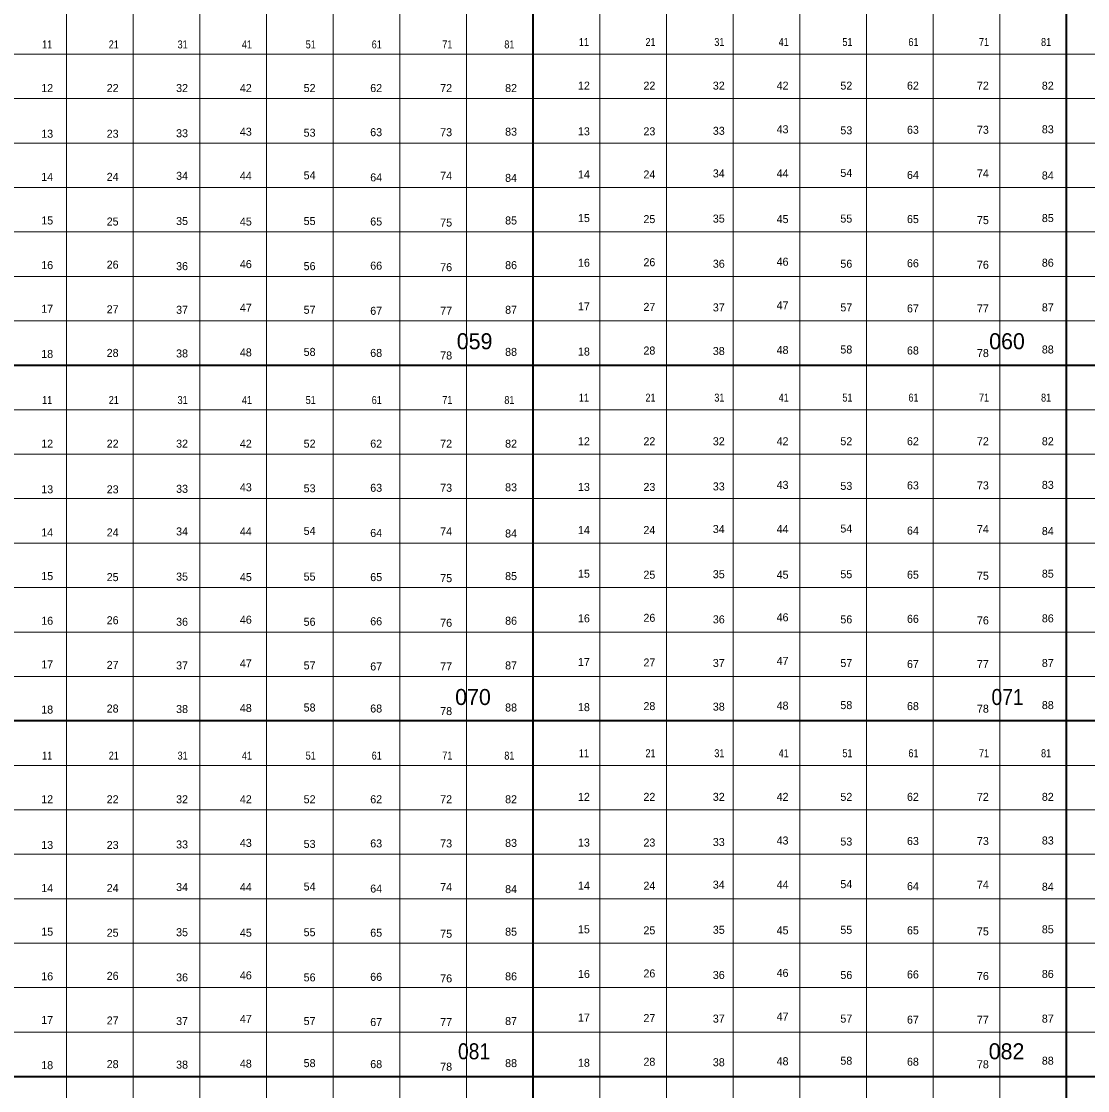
# Model space of a CAD drawing. Extents: x 639000 to 672000, y 222000 to 252000.
# Drawn here: x 660121 to 666119, y 233921 to 239934 of the extents above; entities that cross this region are included whole.
import ezdxf
from ezdxf.enums import TextEntityAlignment as Align

# ---------------------------------------------------------------- set-up
doc = ezdxf.new("R2010")
doc.units = 0
doc.header["$LTSCALE"] = 18
doc.layers.add('1', color=7, linetype='Continuous', lineweight=13)
doc.layers.add('2', color=7, linetype='Continuous')
doc.layers.add('29', color=7, linetype='Continuous')

msp = doc.modelspace()

# ---------------------------------------------------------------- linework, layer by layer
at = {"layer": '1'}
for p, q in [((660375, 224000), (660375, 246000)), ((660750, 224000), (660750, 246000)), ((661125, 224000), (661125, 246000)), ((661500, 224000), (661500, 246000)), ((661875, 224000), (661875, 246000)), ((662250, 224000), (662250, 246000)), ((662625, 224000), (662625, 246000)), ((663375, 230000), (663375, 244000)), ((663750, 230000), (663750, 244000)), ((664125, 230000), (664125, 244000)), ((664500, 230000), (664500, 244000)), ((664875, 230000), (664875, 244000)), ((665250, 230000), (665250, 244000)), ((665625, 230000), (665625, 244000)), ((639000, 239750), (672000, 239750)), ((639000, 239500), (672000, 239500)), ((639000, 239250), (672000, 239250)), ((639000, 239000), (672000, 239000)), ((639000, 238750), (672000, 238750)), ((639000, 238500), (672000, 238500)), ((639000, 238250), (672000, 238250)), ((672000, 237750), (639000, 237750)), ((672000, 237500), (639000, 237500)), ((672000, 237250), (639000, 237250)), ((672000, 237000), (639000, 237000)), ((672000, 236750), (639000, 236750)), ((672000, 236500), (639000, 236500)), ((672000, 236250), (639000, 236250)), ((639000, 235750), (672000, 235750)), ((639000, 235500), (672000, 235500)), ((639000, 235250), (672000, 235250)), ((639000, 235000), (672000, 235000)), ((639000, 234750), (672000, 234750)), ((639000, 234500), (672000, 234500)), ((639000, 234250), (672000, 234250))]:
    msp.add_line(p, q, dxfattribs=at)
at = {"layer": '1', "lineweight": 35}
for p, q in [((663000, 224000), (663000, 246000)), ((666000, 230000), (666000, 244000)), ((639000, 238000), (672000, 238000)), ((672000, 236000), (639000, 236000)), ((639000, 234000), (672000, 234000))]:
    msp.add_line(p, q, dxfattribs=at)

# ---------------------------------------------------------------- texts
at = {"layer": '2'}
for s, p in [('059', (662670.29, 238090.28)), ('060', (665665.2, 238090.28)), ('070', (662661.23, 236089.44)), ('082', (665662.55, 234096.83))]:
    msp.add_text(s, height=90, rotation=359.94, dxfattribs=at).set_placement(p, align=Align.CENTER)
at = {"layer": '2', "width": 0.9}
for s, p in [('071', (665668.41, 236089.44)), ('081', (662667.19, 234096.83))]:
    msp.add_text(s, height=90, rotation=359.94, dxfattribs=at).set_placement(p, align=Align.CENTER)
at = {"layer": '29', "width": 0.85}
for s, p in [('11', (660265.92, 239782.2)), ('21', (660640.53, 239782.2)), ('31', (661027.83, 239782.2)), ('41', (661389.73, 239782.2)), ('51', (661748.47, 239782.2)), ('61', (662119.89, 239782.2)), ('71', (662516.72, 239782.2)), ('81', (662865.93, 239782.2)), ('11', (663285.22, 239795.72)), ('21', (663659.82, 239795.72)), ('31', (664047.12, 239795.72)), ('41', (664409.03, 239795.72)), ('51', (664767.76, 239795.72)), ('61', (665139.19, 239795.72)), ('71', (665536.02, 239795.72)), ('81', (665885.22, 239795.72)), ('11', (663285.22, 237795.72)), ('21', (663659.82, 237795.72)), ('31', (664047.12, 237795.72)), ('41', (664409.03, 237795.72)), ('51', (664767.76, 237795.72)), ('61', (665139.19, 237795.72)), ('71', (665536.02, 237795.72)), ('81', (665885.22, 237795.72)), ('11', (660265.92, 237782.2)), ('21', (660640.53, 237782.2)), ('31', (661027.83, 237782.2)), ('41', (661389.73, 237782.2)), ('51', (661748.47, 237782.2)), ('61', (662119.89, 237782.2)), ('71', (662516.72, 237782.2)), ('81', (662865.93, 237782.2)), ('11', (660265.92, 235782.2)), ('21', (660640.53, 235782.2)), ('31', (661027.83, 235782.2)), ('41', (661389.73, 235782.2)), ('51', (661748.47, 235782.2)), ('61', (662119.89, 235782.2)), ('71', (662516.72, 235782.2)), ('81', (662865.93, 235782.2)), ('11', (663285.22, 235795.72)), ('21', (663659.82, 235795.72)), ('31', (664047.12, 235795.72)), ('41', (664409.03, 235795.72)), ('51', (664767.76, 235795.72)), ('61', (665139.19, 235795.72)), ('71', (665536.02, 235795.72)), ('81', (665885.22, 235795.72))]:
    msp.add_text(s, height=45, dxfattribs=at).set_placement(p, align=Align.CENTER)
at = {"layer": '29'}
for s, p in [('12', (660265.92, 239536.81)), ('22', (660634.18, 239536.81)), ('32', (661024.65, 239536.81)), ('42', (661383.38, 239536.81)), ('52', (661742.11, 239536.81)), ('62', (662116.72, 239536.81)), ('72', (662510.37, 239536.81)), ('82', (662875.45, 239536.81)), ('12', (663285.22, 239550.33)), ('22', (663653.47, 239550.33)), ('32', (664043.95, 239550.33)), ('42', (664402.68, 239550.33)), ('52', (664761.41, 239550.33)), ('62', (665136.01, 239550.33)), ('72', (665529.66, 239550.33)), ('82', (665894.74, 239550.33)), ('13', (663285.22, 239293.4)), ('23', (663653.47, 239293.4)), ('33', (664043.95, 239296.28)), ('43', (664402.68, 239304.94)), ('53', (664761.41, 239299.17)), ('63', (665136.01, 239302.06)), ('73', (665529.67, 239302.06)), ('83', (665894.74, 239304.94)), ('13', (660265.92, 239279.87)), ('23', (660634.18, 239279.87)), ('33', (661024.65, 239282.76)), ('43', (661383.39, 239291.42)), ('53', (661742.11, 239285.65)), ('63', (662116.72, 239288.53)), ('73', (662510.37, 239288.53)), ('83', (662875.45, 239291.42)), ('34', (664043.95, 239056.67)), ('44', (664402.68, 239056.67)), ('54', (664761.41, 239059.55)), ('74', (665529.67, 239056.67)), ('14', (660265.92, 239037.37)), ('24', (660634.18, 239037.37)), ('34', (661024.65, 239043.14)), ('44', (661383.39, 239043.14)), ('54', (661742.11, 239046.03)), ('64', (662116.72, 239034.48)), ('74', (662510.37, 239043.14)), ('84', (662875.45, 239031.6)), ('14', (663285.22, 239050.89)), ('24', (663653.47, 239050.89)), ('64', (665136.01, 239048.01)), ('84', (665894.74, 239045.12)), ('15', (660265.92, 238791.98)), ('25', (660634.18, 238786.21)), ('35', (661024.65, 238789.09)), ('45', (661383.39, 238786.21)), ('55', (661742.11, 238789.09)), ('65', (662116.72, 238786.21)), ('75', (662510.37, 238780.43)), ('85', (662875.45, 238791.98)), ('15', (663285.22, 238805.5)), ('25', (663653.47, 238799.73)), ('35', (664043.95, 238802.61)), ('45', (664402.68, 238799.73)), ('55', (664761.41, 238802.61)), ('65', (665136.01, 238799.73)), ('75', (665529.67, 238793.95)), ('85', (665894.74, 238805.5)), ('16', (660265.92, 238540.82)), ('26', (660634.18, 238543.7)), ('36', (661024.65, 238535.04)), ('46', (661383.39, 238546.59)), ('56', (661742.11, 238535.04)), ('66', (662116.72, 238537.93)), ('76', (662510.37, 238529.27)), ('86', (662875.45, 238540.82)), ('16', (663285.22, 238554.34)), ('26', (663653.47, 238557.22)), ('36', (664043.95, 238548.56)), ('46', (664402.68, 238560.11)), ('56', (664761.41, 238548.56)), ('66', (665136.01, 238551.45)), ('76', (665529.67, 238542.79)), ('86', (665894.74, 238554.34)), ('17', (660265.92, 238295.43)), ('27', (660634.18, 238292.54)), ('37', (661024.65, 238289.65)), ('47', (661383.39, 238301.2)), ('57', (661742.12, 238289.65)), ('67', (662116.72, 238283.88)), ('77', (662510.37, 238283.88)), ('87', (662875.45, 238289.65)), ('17', (663285.22, 238308.95)), ('27', (663653.47, 238306.06)), ('37', (664043.95, 238303.17)), ('47', (664402.68, 238314.72)), ('57', (664761.41, 238303.17)), ('67', (665136.01, 238297.4)), ('77', (665529.67, 238297.4)), ('87', (665894.75, 238303.17)), ('18', (660265.92, 238041.37)), ('28', (660634.18, 238047.15)), ('38', (661024.65, 238044.26)), ('48', (661383.38, 238050.03)), ('58', (661742.11, 238052.92)), ('68', (662116.72, 238047.15)), ('78', (662510.37, 238032.71)), ('88', (662875.45, 238052.92)), ('18', (663285.22, 238054.9)), ('28', (663653.47, 238060.67)), ('38', (664043.95, 238057.78)), ('48', (664402.68, 238063.56)), ('58', (664761.41, 238066.44)), ('68', (665136.01, 238060.67)), ('78', (665529.66, 238046.23)), ('88', (665894.74, 238066.44)), ('12', (663285.22, 237550.33)), ('22', (663653.47, 237550.33)), ('32', (664043.95, 237550.33)), ('42', (664402.68, 237550.33)), ('52', (664761.41, 237550.33)), ('62', (665136.01, 237550.33)), ('72', (665529.66, 237550.33)), ('82', (665894.74, 237550.33)), ('12', (660265.92, 237536.81)), ('22', (660634.18, 237536.81)), ('32', (661024.65, 237536.81)), ('42', (661383.38, 237536.81)), ('52', (661742.11, 237536.81)), ('62', (662116.72, 237536.81)), ('72', (662510.37, 237536.81)), ('82', (662875.45, 237536.81)), ('13', (660265.92, 237279.87)), ('23', (660634.18, 237279.87)), ('33', (661024.65, 237282.76)), ('43', (661383.39, 237291.42)), ('53', (661742.11, 237285.65)), ('63', (662116.72, 237288.53)), ('73', (662510.37, 237288.53)), ('83', (662875.45, 237291.42)), ('13', (663285.22, 237293.4)), ('23', (663653.47, 237293.4)), ('33', (664043.95, 237296.28)), ('43', (664402.68, 237304.94)), ('53', (664761.41, 237299.17)), ('63', (665136.01, 237302.06)), ('73', (665529.67, 237302.06)), ('83', (665894.74, 237304.94)), ('14', (660265.92, 237037.37)), ('24', (660634.18, 237037.37)), ('34', (661024.65, 237043.14)), ('44', (661383.39, 237043.14)), ('54', (661742.11, 237046.03)), ('64', (662116.72, 237034.48)), ('74', (662510.37, 237043.14)), ('84', (662875.45, 237031.6)), ('14', (663285.22, 237050.89)), ('24', (663653.47, 237050.89)), ('34', (664043.95, 237056.67)), ('44', (664402.68, 237056.67)), ('54', (664761.41, 237059.55)), ('64', (665136.01, 237048.01)), ('74', (665529.67, 237056.67)), ('84', (665894.74, 237045.12)), ('15', (660265.92, 236791.98)), ('25', (660634.18, 236786.21)), ('35', (661024.65, 236789.09)), ('45', (661383.39, 236786.21)), ('55', (661742.11, 236789.09)), ('65', (662116.72, 236786.21)), ('75', (662510.37, 236780.43)), ('85', (662875.45, 236791.98)), ('15', (663285.22, 236805.5)), ('25', (663653.47, 236799.73)), ('35', (664043.95, 236802.61)), ('45', (664402.68, 236799.73)), ('55', (664761.41, 236802.61)), ('65', (665136.01, 236799.73)), ('75', (665529.67, 236793.95)), ('85', (665894.74, 236805.5)), ('16', (660265.92, 236540.82)), ('26', (660634.18, 236543.7)), ('36', (661024.65, 236535.04)), ('46', (661383.39, 236546.59)), ('56', (661742.11, 236535.04)), ('66', (662116.72, 236537.93)), ('76', (662510.37, 236529.27)), ('86', (662875.45, 236540.82)), ('16', (663285.22, 236554.34)), ('26', (663653.47, 236557.22)), ('36', (664043.95, 236548.56)), ('46', (664402.68, 236560.11)), ('56', (664761.41, 236548.56)), ('66', (665136.01, 236551.45)), ('76', (665529.67, 236542.79)), ('86', (665894.74, 236554.34)), ('17', (660265.92, 236295.43)), ('27', (660634.18, 236292.54)), ('37', (661024.65, 236289.65)), ('47', (661383.39, 236301.2)), ('57', (661742.12, 236289.65)), ('87', (662875.45, 236289.65)), ('17', (663285.22, 236308.95)), ('27', (663653.47, 236306.06)), ('37', (664043.95, 236303.17)), ('47', (664402.68, 236314.72)), ('57', (664761.41, 236303.17)), ('67', (665136.01, 236297.4)), ('77', (665529.67, 236297.4)), ('87', (665894.75, 236303.17)), ('67', (662116.72, 236283.88)), ('77', (662510.37, 236283.88)), ('28', (660634.18, 236047.15)), ('48', (661383.38, 236050.03)), ('58', (661742.11, 236052.92)), ('68', (662116.72, 236047.15)), ('88', (662875.45, 236052.92)), ('18', (663285.22, 236054.9)), ('28', (663653.47, 236060.67)), ('38', (664043.95, 236057.78)), ('48', (664402.68, 236063.56)), ('58', (664761.41, 236066.44)), ('68', (665136.01, 236060.67)), ('78', (665529.66, 236046.23)), ('88', (665894.74, 236066.44)), ('18', (660265.92, 236041.37)), ('38', (661024.65, 236044.26)), ('78', (662510.37, 236032.71)), ('12', (660265.92, 235536.81)), ('22', (660634.18, 235536.81)), ('32', (661024.65, 235536.81)), ('42', (661383.38, 235536.81)), ('52', (661742.11, 235536.81)), ('62', (662116.72, 235536.81)), ('72', (662510.37, 235536.81)), ('82', (662875.45, 235536.81)), ('12', (663285.22, 235550.33)), ('22', (663653.47, 235550.33)), ('32', (664043.95, 235550.33)), ('42', (664402.68, 235550.33)), ('52', (664761.41, 235550.33)), ('62', (665136.01, 235550.33)), ('72', (665529.66, 235550.33)), ('82', (665894.74, 235550.33)), ('13', (660265.92, 235279.87)), ('23', (660634.18, 235279.87)), ('33', (661024.65, 235282.76)), ('43', (661383.39, 235291.42)), ('53', (661742.11, 235285.65)), ('63', (662116.72, 235288.53)), ('73', (662510.37, 235288.53)), ('83', (662875.45, 235291.42)), ('13', (663285.22, 235293.4)), ('23', (663653.47, 235293.4)), ('33', (664043.95, 235296.28)), ('43', (664402.68, 235304.94)), ('53', (664761.41, 235299.17)), ('63', (665136.01, 235302.06)), ('73', (665529.67, 235302.06)), ('83', (665894.74, 235304.94)), ('14', (660265.92, 235037.37)), ('24', (660634.18, 235037.37)), ('34', (661024.65, 235043.14)), ('44', (661383.39, 235043.14)), ('54', (661742.11, 235046.03)), ('64', (662116.72, 235034.48)), ('74', (662510.37, 235043.14)), ('84', (662875.45, 235031.6)), ('14', (663285.22, 235050.89)), ('24', (663653.47, 235050.89)), ('34', (664043.95, 235056.67)), ('44', (664402.68, 235056.67)), ('54', (664761.41, 235059.55)), ('64', (665136.01, 235048.01)), ('74', (665529.67, 235056.67)), ('84', (665894.74, 235045.12)), ('15', (660265.92, 234791.98)), ('25', (660634.18, 234786.21)), ('35', (661024.65, 234789.09)), ('45', (661383.39, 234786.21)), ('55', (661742.11, 234789.09)), ('65', (662116.72, 234786.21)), ('85', (662875.45, 234791.98)), ('15', (663285.22, 234805.5)), ('25', (663653.47, 234799.73)), ('35', (664043.95, 234802.61)), ('45', (664402.68, 234799.73)), ('55', (664761.41, 234802.61)), ('65', (665136.01, 234799.73)), ('75', (665529.67, 234793.95)), ('85', (665894.74, 234805.5)), ('75', (662510.37, 234780.43)), ('26', (660634.18, 234543.7)), ('46', (661383.39, 234546.59)), ('16', (663285.22, 234554.34)), ('26', (663653.47, 234557.22)), ('36', (664043.95, 234548.56)), ('46', (664402.68, 234560.11)), ('56', (664761.41, 234548.56)), ('66', (665136.01, 234551.45)), ('76', (665529.67, 234542.79)), ('86', (665894.74, 234554.34)), ('16', (660265.92, 234540.82)), ('36', (661024.65, 234535.04)), ('56', (661742.11, 234535.04)), ('66', (662116.72, 234537.93)), ('76', (662510.37, 234529.27)), ('86', (662875.45, 234540.82)), ('17', (663285.22, 234308.95)), ('27', (663653.47, 234306.06)), ('37', (664043.95, 234303.17)), ('47', (664402.68, 234314.72)), ('57', (664761.41, 234303.17)), ('87', (665894.75, 234303.17)), ('17', (660265.92, 234295.43)), ('27', (660634.18, 234292.54)), ('37', (661024.65, 234289.65)), ('47', (661383.39, 234301.2)), ('57', (661742.12, 234289.65)), ('67', (662116.72, 234283.88)), ('77', (662510.37, 234283.88)), ('87', (662875.45, 234289.65)), ('67', (665136.01, 234297.4)), ('77', (665529.67, 234297.4)), ('48', (664402.68, 234063.56)), ('58', (664761.41, 234066.44)), ('88', (665894.74, 234066.44)), ('18', (660265.92, 234041.37)), ('28', (660634.18, 234047.15)), ('38', (661024.65, 234044.26)), ('48', (661383.38, 234050.03)), ('58', (661742.11, 234052.92)), ('68', (662116.72, 234047.15)), ('78', (662510.37, 234032.71)), ('88', (662875.45, 234052.92)), ('18', (663285.22, 234054.9)), ('28', (663653.47, 234060.67)), ('38', (664043.95, 234057.78)), ('68', (665136.01, 234060.67)), ('78', (665529.66, 234046.23))]:
    msp.add_text(s, height=45, dxfattribs=at).set_placement(p, align=Align.CENTER)

doc.saveas('drawing.dxf')
